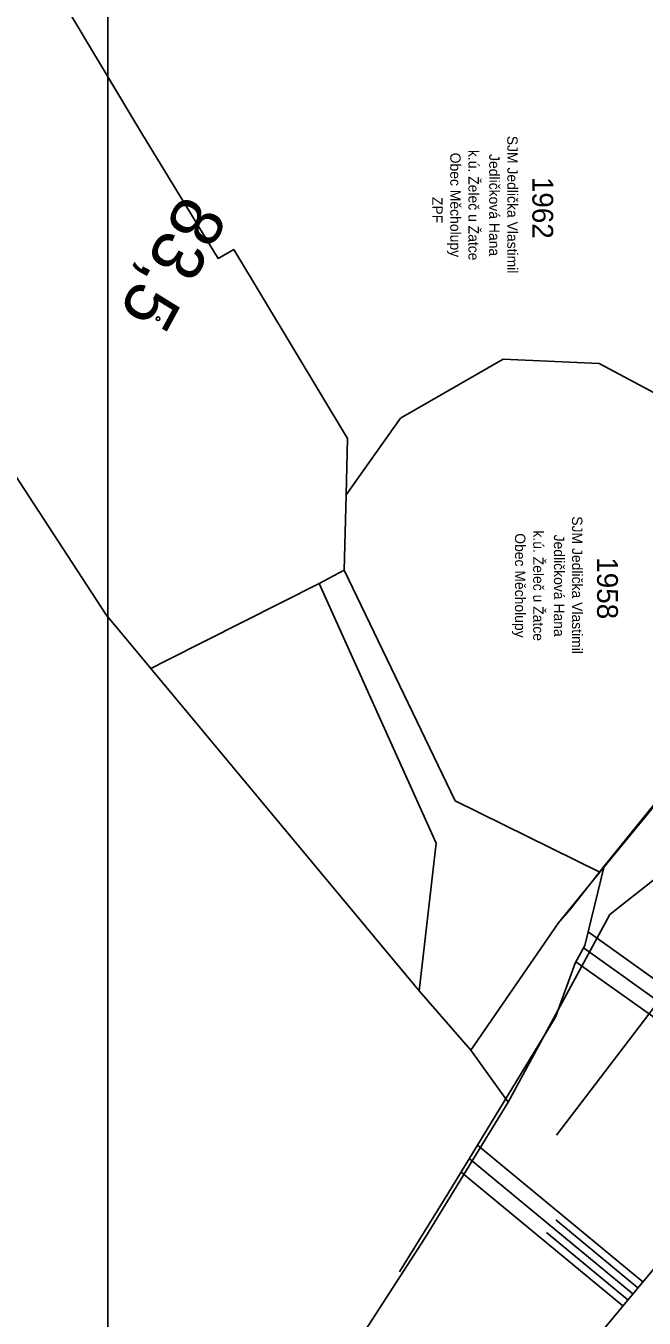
# Model space of a CAD drawing. Extents: x -801372 to -800991, y -1017235 to -1016862.
# Drawn here: x -801225.8 to -801166.4, y -1017121 to -1016996.8 of the extents above; entities that cross this region are included whole.
import ezdxf

# ---------------------------------------------------------------- set-up
doc = ezdxf.new("R2010")
doc.units = 0
for name, color, linetype in [('09 - stávající terén', 7, 'Continuous'), ('19 - katastr', 7, 'Continuous'), ('19b - katastr - hranice SŽDC', 7, 'Continuous'), ('19b - katastr popisy', 7, 'Continuous'), ('23 - neviditelná', 7, 'Continuous'), ('Hranice parcel', 7, 'Continuous'), ('Vrstva 17', 7, 'Continuous'), ('Vrstva 25', 7, 'Continuous'), ('Vrstva 48 - svahy', 7, 'Continuous'), ('Vrstva 7', 7, 'Continuous'), ('Značky budov', 7, 'Continuous')]:
    doc.layers.add(name, color=color, linetype=linetype)

# ---------------------------------------------------------------- blocks, each defined once
blk = doc.blocks.new('4.02125')
at = {"layer": 'Značky budov'}
blk.add_circle((-0.01, 0), 0.175, dxfattribs=at)

msp = doc.modelspace()

# ---------------------------------------------------------------- linework, layer by layer
at = {"layer": '09 - stávající terén'}
for p, q in [((-801165.49, -1017071.71), (-801170.28, -1017077.62)), ((-801170.28, -1017077.62), (-801172.14, -1017085.23)), ((-801172.14, -1017085.23), (-801173.05, -1017086.92)), ((-801173.05, -1017086.92), (-801174.95, -1017092.11)), ((-801174.95, -1017092.11), (-801185.3, -1017109.1)), ((-801185.3, -1017109.1), (-801189.92, -1017116.58)), ((-801159.87, -1017109.48), (-801170.36, -1017122.16))]:
    msp.add_line(p, q, dxfattribs=at)
at = {"layer": '19 - katastr'}
for p, q in [((-801195.24, -1017049.16), (-801195.06, -1017041.91)), ((-801195.24, -1017049.16), (-801195.06, -1017041.91)), ((-801197.66, -1017050.43), (-801195.24, -1017049.16)), ((-801188.04, -1017089.59), (-801213.83, -1017058.6)), ((-801183.07, -1017095.3), (-801188.04, -1017089.59)), ((-801179.48, -1017100.28), (-801183.07, -1017095.3))]:
    msp.add_line(p, q, dxfattribs=at)
for points in [[(-801195.06, -1017041.91), (-801194.93, -1017036.49), (-801202.91, -1017023.23), (-801205.86, -1017018.33), (-801207.37, -1017019.2), (-801214.69, -1017007.21), (-801225.84, -1016988.55), (-801228.75, -1016990.75), (-801232.81, -1016983.18)], [(-801236.03, -1016985.46), (-801248.21, -1017007.29), (-801218.11, -1017053.46), (-801213.83, -1017058.6)], [(-801195.06, -1017041.91), (-801194.93, -1017036.49), (-801202.91, -1017023.23), (-801205.86, -1017018.33), (-801207.37, -1017019.2), (-801214.69, -1017007.21), (-801217.95, -1017001.75)], [(-801151.48, -1017039.58), (-801170.76, -1017029.31), (-801179.96, -1017028.88), (-801189.85, -1017034.56), (-801195.06, -1017041.91)], [(-801151.48, -1017039.58), (-801170.76, -1017029.31), (-801179.96, -1017028.88), (-801189.85, -1017034.56), (-801195.06, -1017041.91)], [(-801170.68, -1017078.19), (-801161.48, -1017067), (-801155.16, -1017055.94), (-801148.85, -1017042.19), (-801151.48, -1017039.58)], [(-801170.68, -1017078.19), (-801184.59, -1017071.32), (-801195.24, -1017049.16)], [(-801213.83, -1017058.6), (-801212.26, -1017057.81), (-801197.66, -1017050.43)], [(-801213.83, -1017058.6), (-801212.26, -1017057.81), (-801197.66, -1017050.43)], [(-801188.04, -1017089.59), (-801186.42, -1017075.39), (-801197.66, -1017050.43)], [(-801183.07, -1017095.3), (-801174.66, -1017083.05), (-801170.68, -1017078.19)]]:
    msp.add_lwpolyline(points, dxfattribs=at)
at = {"layer": '19b - katastr - hranice SŽDC'}
for points in [[(-801179.48, -1017100.28), (-801169.74, -1017082.25), (-801157.42, -1017072.56), (-801145.88, -1017061.68), (-801137.41, -1017046.38), (-801149.55, -1017039.8), (-801149.01, -1017037.86)], [(-801217.95, -1017153.62), (-801211.22, -1017145.68), (-801196.91, -1017127.94), (-801187.5, -1017113.35), (-801179.48, -1017100.28)]]:
    msp.add_lwpolyline(points, dxfattribs=at)
at = {"layer": '23 - neviditelná'}
msp.add_lwpolyline([(-801217.95, -1016905.67), (-800990.79, -1016905.67), (-800990.79, -1017234.77), (-801217.95, -1017234.77)], close=True, dxfattribs=at)
at = {"layer": 'Hranice parcel'}
msp.add_line((-801197.66, -1017050.43), (-801195.24, -1017049.16), dxfattribs=at)
at = {"layer": 'Vrstva 17'}
for p, q in [((-801165.49, -1017071.71), (-801170.28, -1017077.62)), ((-801170.28, -1017077.62), (-801173.45, -1017081.64)), ((-801174.68, -1017083.09), (-801173.45, -1017081.64))]:
    msp.add_line(p, q, dxfattribs=at)
at = {"layer": 'Vrstva 25'}
msp.add_line((-801174.85, -1017103.46), (-801151.85, -1017073.26), dxfattribs=at)
at = {"layer": 'Vrstva 48 - svahy'}
for p, q in [((-801151.82, -1017098.2), (-801171.82, -1017083.93)), ((-801152.69, -1017099.43), (-801172.26, -1017085.46)), ((-801153.56, -1017100.65), (-801172.98, -1017086.79)), ((-801166.55, -1017117.56), (-801182.44, -1017104.41)), ((-801167.51, -1017118.72), (-801183.23, -1017105.71)), ((-801168.47, -1017119.87), (-801184.02, -1017107)), ((-801167.03, -1017118.14), (-801174.93, -1017111.6)), ((-801167.99, -1017119.29), (-801175.81, -1017112.82))]:
    msp.add_line(p, q, dxfattribs=at)

# ---------------------------------------------------------------- block references
msp.add_blockref('4.02125', (-801213.12, -1017025))

# ---------------------------------------------------------------- texts
at = {"layer": '19b - katastr popisy'}
for s, height, p in [('SJM Jedlička Vlastimil', 1.0001, (-801179.58, -1017007.41)), ('Obec Měcholupy', 1.0001, (-801185.06, -1017009.04)), ('k.ú. Želeč u Žatce ', 1.0001, (-801183.31, -1017008.77)), ('Jedličková Hana', 1.0001, (-801181.32, -1017009.17)), ('1962', 2, (-801177.17, -1017011.36)), ('ZPF', 1, (-801186.79, -1017013.29)), ('SJM Jedlička Vlastimil', 1.0001, (-801173.36, -1017043.98)), ('Obec Měcholupy', 1.0001, (-801178.84, -1017045.61)), ('k.ú. Želeč u Žatce ', 1.0001, (-801177.09, -1017045.34)), ('Jedličková Hana', 1.0001, (-801175.1, -1017045.74)), ('1958', 2, (-801170.95, -1017047.92))]:
    msp.add_text(s, height=height, rotation=270, dxfattribs=at).set_placement(p)
at = {"layer": 'Vrstva 7'}
msp.add_text('83,5', height=5, rotation=241.5341, dxfattribs=at).set_placement((-801210.74, -1017012.88))

doc.saveas('drawing.dxf')
